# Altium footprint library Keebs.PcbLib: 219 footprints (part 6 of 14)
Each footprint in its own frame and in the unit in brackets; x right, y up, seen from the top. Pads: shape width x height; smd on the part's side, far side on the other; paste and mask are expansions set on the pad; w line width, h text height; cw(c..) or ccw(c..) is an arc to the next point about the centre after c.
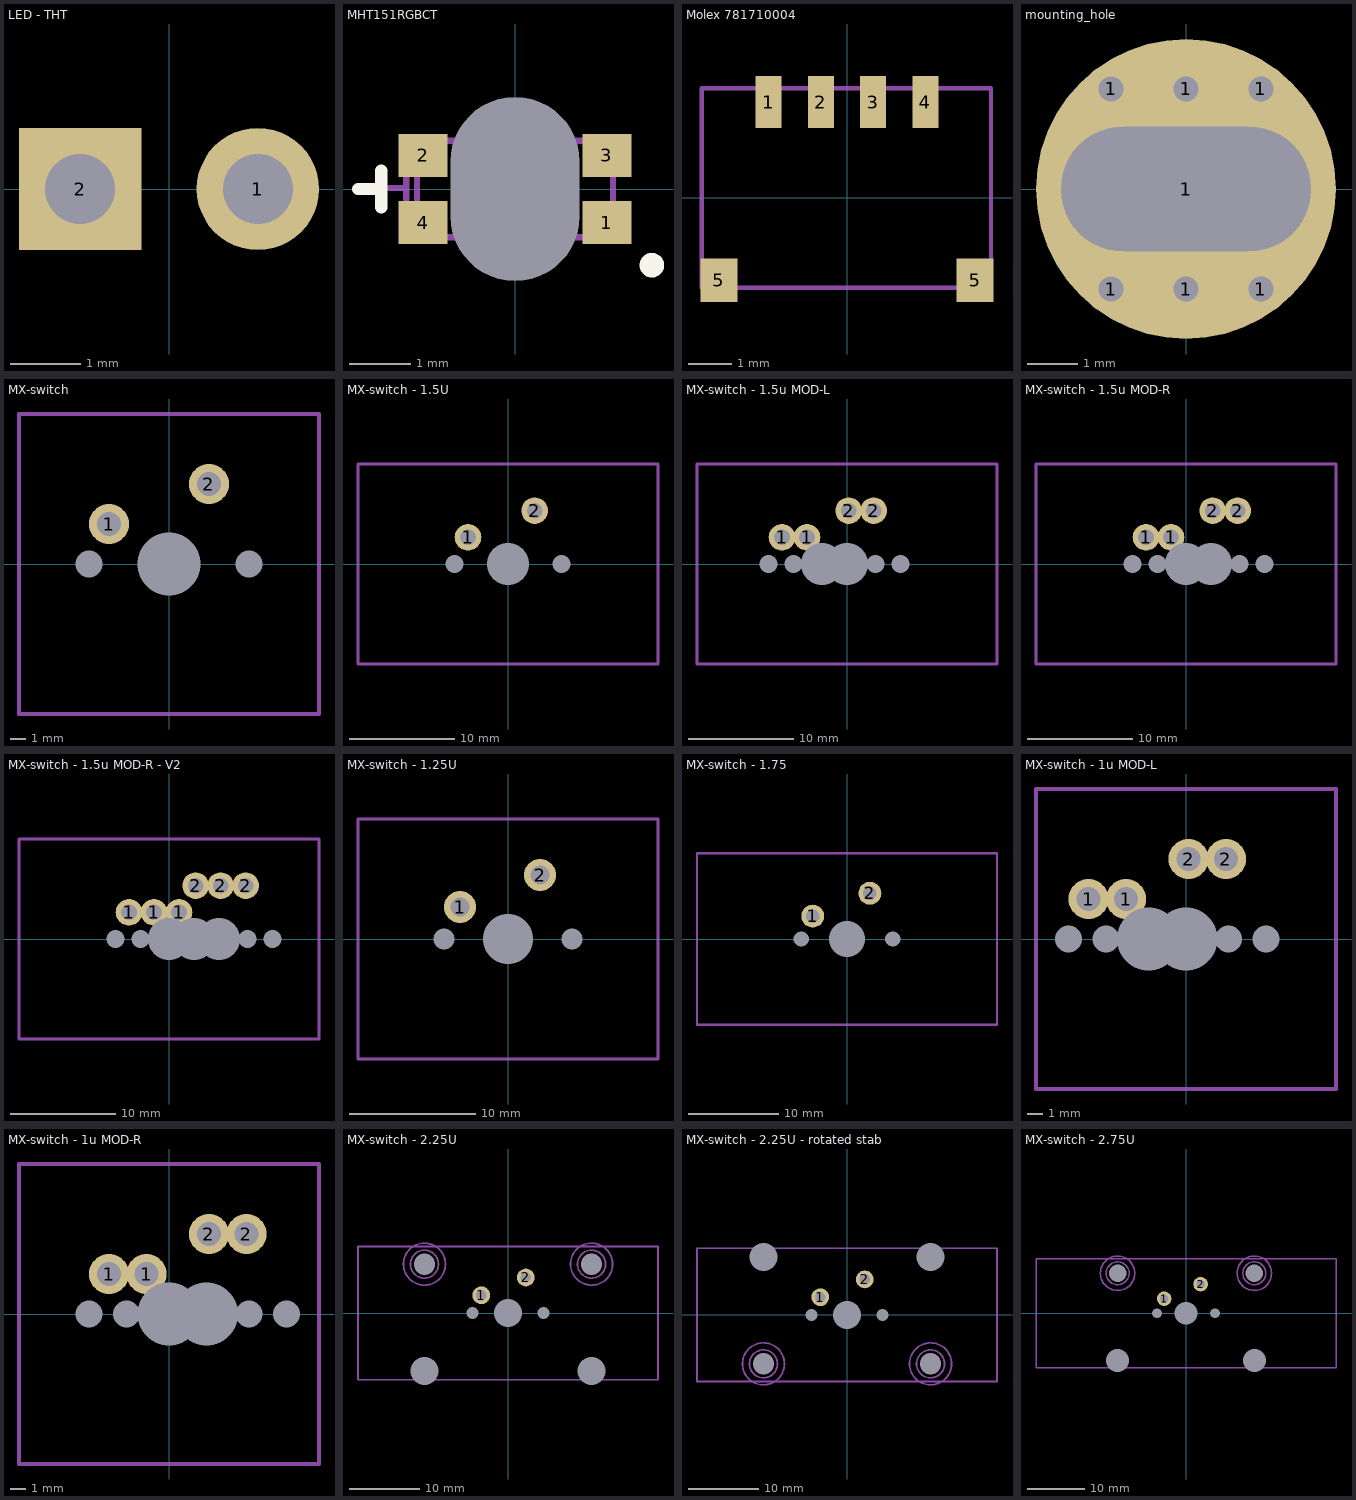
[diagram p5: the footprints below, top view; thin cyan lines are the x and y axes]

## LED - THT [mm]
pads (3):
  round 1.75 hole 1 mask+0.102: 1(1.27,0)
  rect 1.75x1.75 hole 1 mask+0.102: 2(-1.27,0)
  round 1 on Mech14: ""(0,0)
Mechanical 14:
  text ".Designator" at 3.575,-3.7 h0.7

## MHT151RGBCT [mm] "For MHT151RGBCT/E6CC1205RGBC3UDA"
pads (5):
  rect 0.8x0.7 smd: 1(1.5,-0.55) 2(-1.5,0.55) 3(1.5,0.55) 4(-1.5,-0.55)
  round 0 hole 2.1 slot 3 at 90 deg unplated: ""(0,0)
Top Overlay:
  circle w0.2: c2.235,-1.245 r0.1
  lines w0.2: -2.565,0 -2.184,0 ; -2.184,-0.3 -2.184,0.3
Mechanical 13:
  lines w0.1: -2.057,0.018 -1.778,0.018 ; -1.778,-0.167 -1.778,0.203 ; -1.6,-0.787 -1.6,0.787 1.6,0.787 1.6,-0.787 -1.6,-0.787
  text ".Designator" at -1.372,-0.33 h0.5
3D body "APTBD3216.STEP": height 0.33, standoff -1.48, extent -1.6,-0.8 1.6,0.8

## Molex 781710004 [mm]
pads (6):
  rect 0.6x1.2 smd: 1(-1.8,2.2) 2(-0.6,2.2) 3(0.6,2.2) 4(1.8,2.2)
  rect 0.85x1 smd: 5(-2.94,-1.887) 5(2.94,-1.887)
Mechanical 13:
  lines w0.1: -3.327,-2.057 -3.327,2.515 3.302,2.515 3.302,-2.057 -3.327,-2.057
  text ".Designator" at -2.891,-0.338 h0.7
3D body "781710004.stp": height 1.5, standoff 0.05, extent -3.3,-2.047 3.3,2.483

## mounting_hole [mm]
pads (7):
  round 1 hole 0.5 paste+0 mask+0: 1(-1.5,-2) 1(-1.5,2) 1(0,-2) 1(0,2) 1(1.5,-2) 1(1.5,2)
  round 6 hole 2.5 slot 5 at 0 deg: 1(0,0)

## MX-switch [mm]
pads (5):
  round 2.54 hole 1.5 mask-0.5: 1(-3.81,2.54) 2(2.54,5.08)
  round 1 hole 1.7 unplated: ""(-5.08,0) ""(5.08,0)
  round 1 hole 4 unplated: ""(0,0)
Mechanical 13:
  lines w0.254: -9.525,-9.525 9.525,-9.525 9.525,9.525 -9.525,9.525 -9.525,-9.525
  text ".Designator" at -3.575,-3.7 h0.7

## MX-switch - 1.5U [mm]
pads (6):
  round 2.54 hole 1.5 mask-0.5: 1(-3.81,2.54) 2(2.54,5.08)
  round 1 hole 1.7 unplated: ""(-5.08,0) ""(5.08,0)
  round 1 on Mech13: ""(0,0)
  round 1 hole 4 unplated: ""(0,0)
Mechanical 13:
  lines w0.254: -14.287,-9.525 14.287,-9.525 14.287,9.525 -14.287,9.525 -14.287,-9.525
  text ".Designator" at -3.825,-3.375 h0.7

## MX-switch - 1.5u MOD-L [mm]
pads (14):
  round 2.54 hole 1.5 mask-0.5: 1(-6.191,2.54) 1(-3.81,2.54) 2(0.159,5.08) 2(2.54,5.08)
  round 1 hole 1.7 unplated: ""(-7.461,0) ""(-5.08,0) ""(2.699,0) ""(5.08,0)
  round 1 on Mech13: ""(-4.763,0) ""(-2.381,0) ""(0,0) ""(4.763,0)
  round 1 hole 4 unplated: ""(-2.381,0) ""(0,0)
Mechanical 13:
  lines w0.254: -14.287,-9.525 -14.287,9.525 14.287,9.525 14.287,-9.525 -14.287,-9.525
  text ".Designator" at 2.9,2.625 h0.7

## MX-switch - 1.5u MOD-R [mm]
pads (14):
  round 2.54 hole 1.5 mask-0.5: 1(-3.81,2.54) 1(-1.429,2.54) 2(2.54,5.08) 2(4.921,5.08)
  round 1 hole 1.7 unplated: ""(-5.08,0) ""(-2.699,0) ""(5.08,0) ""(7.461,0)
  round 1 on Mech13: ""(-2.381,0) ""(0,0) ""(2.381,0) ""(4.763,0)
  round 1 hole 4 unplated: ""(0,0) ""(2.381,0)
Mechanical 13:
  lines w0.254: -14.287,-9.525 14.287,-9.525 14.287,9.525 -14.287,9.525 -14.287,-9.525
  text ".Designator" at -10.675,-5.325 h0.7

## MX-switch - 1.5u MOD-R - V2 [mm]
pads (17):
  round 2.54 hole 1.5 mask-0.5: 1(-3.81,2.54) 1(-1.429,2.54) 1(0.953,2.54) 2(2.54,5.08) 2(4.921,5.08) 2(7.302,5.08)
  round 1 hole 1.7 unplated: ""(-5.08,0) ""(-2.699,0) ""(7.461,0) ""(9.842,0)
  round 1 on Mech13: ""(-2.381,0) ""(0,0) ""(2.381,0) ""(4.763,0)
  round 1 hole 4 unplated: ""(0,0) ""(2.381,0) ""(4.763,0)
Mechanical 13:
  lines w0.254: -14.287,-9.525 -14.287,9.525 14.287,9.525 14.287,-9.525 -14.287,-9.525
  text ".Designator" at -10.675,-5.325 h0.7

## MX-switch - 1.25U [mm]
pads (6):
  round 2.54 hole 1.5 mask-0.5: 1(-3.81,2.54) 2(2.54,5.08)
  round 1 hole 1.7 unplated: ""(-5.08,0) ""(5.08,0)
  round 1 on Mech13: ""(0,0)
  round 1 hole 4 unplated: ""(0,0)
Mechanical 13:
  lines w0.254: -11.906,-9.525 -11.906,9.525 11.906,9.525 11.906,-9.525 -11.906,-9.525
  text ".Designator" at -3.425,-3.425 h0.7

## MX-switch - 1.75 [mm]
pads (6):
  round 2.54 hole 1.5 mask-0.5: 1(-3.81,2.54) 2(2.54,5.08)
  round 1 hole 1.7 unplated: ""(-5.08,0) ""(5.08,0)
  round 1 on Mech13: ""(0,0)
  round 1 hole 4 unplated: ""(0,0)
Mechanical 13:
  lines w0.254: -16.669,-9.525 16.669,-9.525 16.669,9.525 -16.669,9.525 -16.669,-9.525
  text ".Designator" at -3.825,-3.375 h0.7

## MX-switch - 1u MOD-L [mm]
pads (13):
  round 2.54 hole 1.5 mask-0.5: 1(-6.191,2.54) 1(-3.81,2.54) 2(0.159,5.08)
  round 2.54 hole 1.499 mask-0.5: 2(2.54,5.08)
  round 1 hole 1.7 unplated: ""(-7.461,0) ""(-5.08,0) ""(2.699,0) ""(5.08,0)
  round 1 on Mech13: ""(-2.381,0) ""(0,0) ""(2.381,0)
  round 1 hole 4 unplated: ""(-2.381,0) ""(0,0)
Mechanical 13:
  lines w0.254: -9.525,-9.525 -9.525,9.525 9.525,9.525 9.525,-9.525 -9.525,-9.525
  text ".Designator" at -1.925,-7.85 h0.7

## MX-switch - 1u MOD-R [mm]
pads (14):
  round 2.54 hole 1.5 mask-0.5: 1(-3.81,2.54) 1(-1.429,2.54) 2(2.54,5.08) 2(4.921,5.08)
  round 1 hole 1.7 unplated: ""(-5.08,0) ""(-2.699,0) ""(5.08,0) ""(7.461,0)
  round 1 on Mech13: ""(-4.763,0) ""(-2.381,0) ""(0,0) ""(2.381,0)
  round 1 hole 4 unplated: ""(0,0) ""(2.381,0)
Mechanical 13:
  lines w0.254: -9.525,-9.525 9.525,-9.525 9.525,9.525 -9.525,9.525 -9.525,-9.525
  text ".Designator" at -4.225,-8.325 h0.7

## MX-switch - 2.25U [mm]
pads (10):
  round 2.54 hole 1.5 mask-0.5: 1(-3.81,2.54) 2(2.54,5.08)
  round 1.524 hole 4 unplated: ""(-11.938,-8.255) ""(11.938,-8.255)
  round 1.524 hole 3.048 unplated: ""(-11.938,6.985) ""(11.938,6.985)
  round 1 hole 1.7 unplated: ""(-5.08,0) ""(5.08,0)
  round 1 on Mech13: ""(0,0)
  round 1 hole 4 unplated: ""(0,0)
Mechanical 13:
  lines w0.254: -21.431,-9.525 21.431,-9.525 21.431,9.525 -21.431,9.525 -21.431,-9.525
  text ".Designator" at -3.825,-3.375 h0.7
Mechanical 15:
  circle w0.254: c-11.938,6.985 r2
  circle w0.254: c-11.938,6.985 r3
  circle w0.254: c11.938,6.985 r2
  circle w0.254: c11.938,6.985 r3

## MX-switch - 2.25U - rotated stab [mm]
pads (10):
  round 2.54 hole 1.5 mask-0.5: 1(-3.81,2.54) 2(2.54,5.08)
  round 1.524 hole 3.048 unplated: ""(-11.938,-6.985) ""(11.938,-6.985)
  round 1.524 hole 4 unplated: ""(-11.938,8.255) ""(11.938,8.255)
  round 1 hole 1.7 unplated: ""(-5.08,0) ""(5.08,0)
  round 1 on Mech13: ""(0,0)
  round 1 hole 4 unplated: ""(0,0)
Mechanical 13:
  lines w0.254: -21.431,-9.525 21.431,-9.525 21.431,9.525 -21.431,9.525 -21.431,-9.525
  text ".Designator" at -3.825,-3.375 h0.7
Mechanical 15:
  circle w0.254: c11.938,-6.985 r3
  circle w0.254: c11.938,-6.985 r2
  circle w0.254: c-11.938,-6.985 r3
  circle w0.254: c-11.938,-6.985 r2

## MX-switch - 2.75U [mm]
pads (10):
  round 2.54 hole 1.5 mask-0.5: 1(-3.81,2.54) 2(2.54,5.08)
  round 1.524 hole 4 unplated: ""(-11.938,-8.255) ""(11.938,-8.255)
  round 1.524 hole 3.048 unplated: ""(-11.938,6.985) ""(11.938,6.985)
  round 1 hole 1.7 unplated: ""(-5.08,0) ""(5.08,0)
  round 1 on Mech13: ""(0,0)
  round 1 hole 4 unplated: ""(0,0)
Mechanical 13:
  lines w0.254: -26.194,-9.525 -26.194,9.525 26.194,9.525 26.194,-9.525 -26.194,-9.525
  text ".Designator" at -3.825,-3.375 h0.7
Mechanical 15:
  circle w0.254: c11.938,6.985 r3
  circle w0.254: c11.938,6.985 r2
  circle w0.254: c-11.938,6.985 r3
  circle w0.254: c-11.938,6.985 r2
